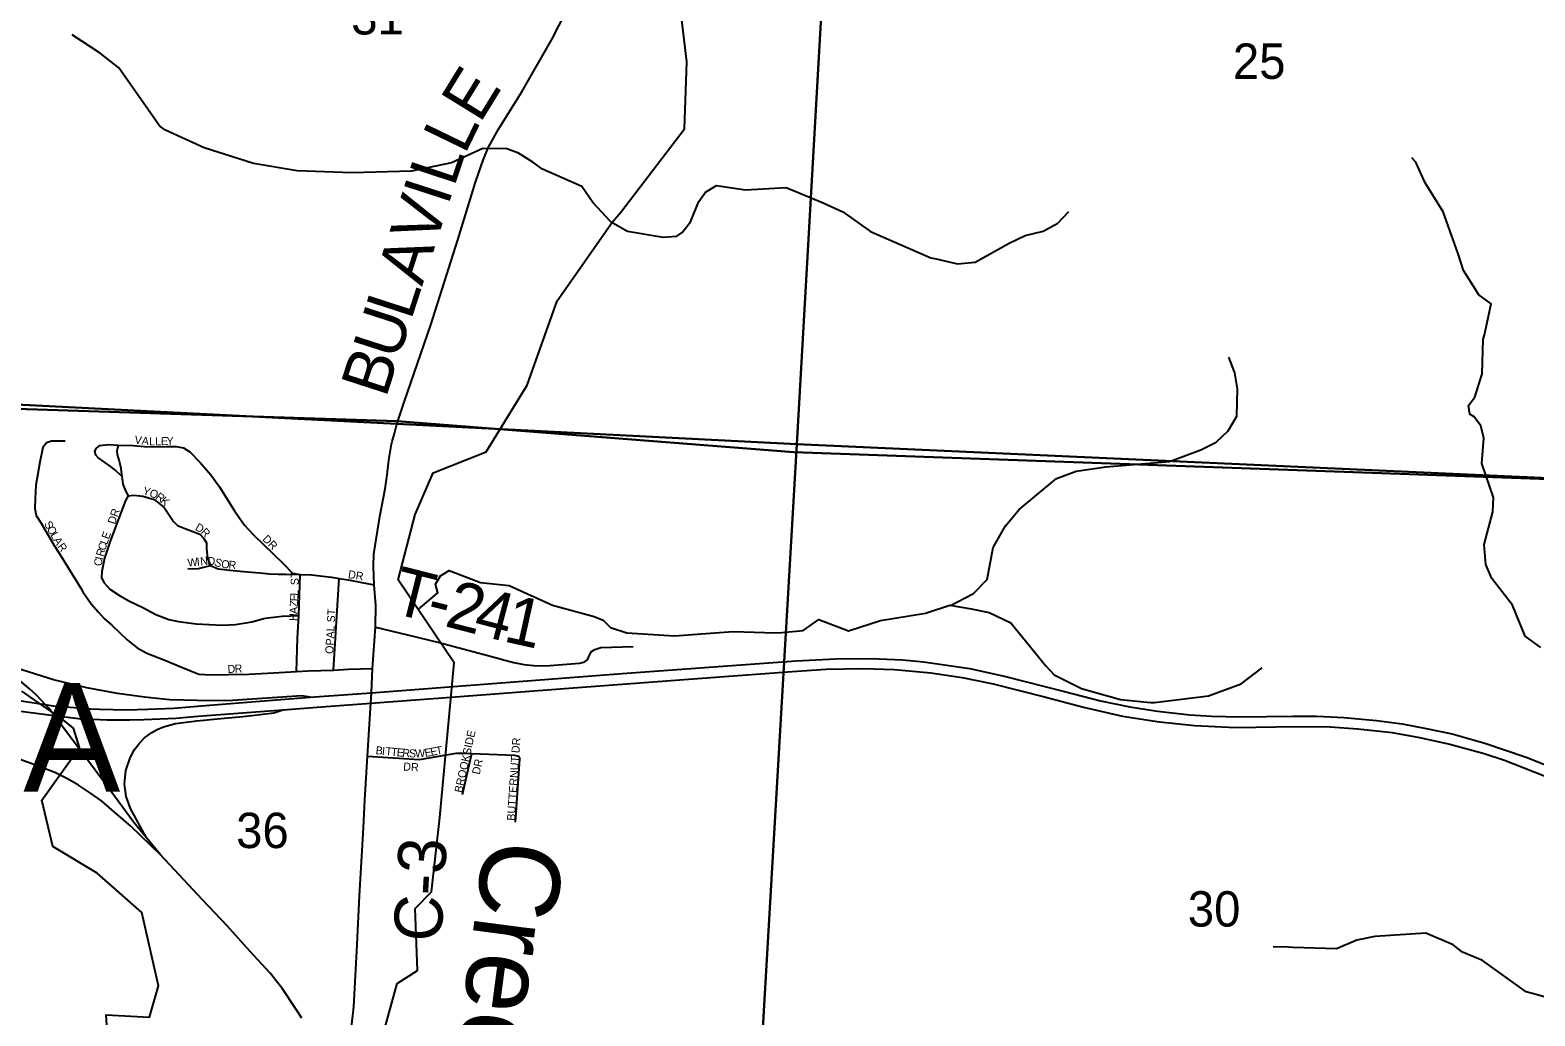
# Model space of a CAD drawing. Extents: x 1878108 to 2183446, y 146837 to 508383.
# Drawn here: x 2047624 to 2057027, y 304899 to 311060 of the extents above; entities that cross this region are included whole.
import ezdxf

# ---------------------------------------------------------------- set-up
doc = ezdxf.new("R2010")
doc.units = 0
for name, color, linetype in [('GM_X_County_Road', 7, 'Continuous'), ('GM_X_County_Road_Text', 7, 'Continuous'), ('GM_X_Interchange_Ramps', 7, 'Continuous'), ('GM_X_Minor_River', 7, 'Continuous'), ('GM_X_Minor_River_Text', 7, 'Continuous'), ('GM_X_Section', 7, 'Continuous'), ('GM_X_Section_Text', 7, 'Continuous'), ('GM_X_State_Route', 7, 'Continuous'), ('GM_X_State_Shield', 7, 'Continuous'), ('GM_X_Township', 7, 'Continuous'), ('GM_X_Township_Road', 7, 'Continuous'), ('GM_X_Township_Road_Text', 7, 'Continuous'), ('GM_X_Township_ROW', 7, 'Continuous'), ('GM_X_Township_Subdivision', 7, 'Continuous'), ('GM_X_Township_Subdivision_Text', 7, 'Continuous'), ('GM_X_US_Route', 7, 'Continuous')]:
    doc.layers.add(name, color=color, linetype=linetype)

msp = doc.modelspace()

# ---------------------------------------------------------------- linework, layer by layer
at = {"layer": 'GM_X_County_Road'}
for points in [[(2049900.5, 308539.7), (2049914, 308588.3), (2049923, 308616.3), (2049961.5, 308735.4), (2050066.6, 309037.3), (2050127.4, 309218.6), (2050297.7, 309749.4), (2050407.2, 310109.9), (2050456.9, 310252.5), (2050489, 310327.7), (2050550.9, 310440.5), (2050695.8, 310674.9), (2050887.1, 311005.6), (2051090.5, 311404.8)], [(2049886.4, 308488.4), (2049900.5, 308539.7)], [(2049772.1, 307646.4), (2049770.2, 307710.4), (2049772.5, 307785.6), (2049808.9, 308020), (2049843.2, 308193.6), (2049855.4, 308279.8), (2049865.3, 308371.6), (2049881.9, 308472.2), (2049886.4, 308488.4)], [(2049520.9, 304582.1), (2049576.5, 304628.2), (2049602.6, 304667.2), (2049614.4, 304708.6), (2049626.2, 304773.7), (2049646.3, 304955.9), (2049667.6, 305345.1), (2049683, 305649.1), (2049706.7, 306075), (2049716.1, 306250.1), (2049732.7, 306522.2), (2049753.9, 306853.8), (2049757.2, 306919.2), (2049764.7, 307070.1), (2049782.4, 307328.9), (2049784.6, 307463.8), (2049773.6, 307593.1), (2049772.1, 307646.4)]]:
    msp.add_lwpolyline(points, dxfattribs=at)
at = {"layer": 'GM_X_Interchange_Ramps'}
for points in [[(2049373.5, 306891.7), (2049322.2, 306899.8), (2048857.3, 306867.2), (2048669, 306869.5), (2048496.5, 306874.9), (2048339, 306891), (2048170.4, 306914.6), (2047978.2, 306949.3), (2047769.9, 307000.1), (2047572.7, 307062.1), (2047428.9, 307110.4), (2047110.9, 307230.7), (2046902.7, 307301.3)], [(2048351.8, 306011.7), (2048251, 306195.3), (2048223.7, 306269.7), (2048215, 306347.9), (2048222.5, 306432.2), (2048248.5, 306511.6), (2048277, 306564.9), (2048306.8, 306604.6), (2048339, 306636.8), (2048384.9, 306670.3), (2048417.2, 306690.1), (2048456.8, 306705), (2048532.5, 306726.1), (2048667, 306743.4), (2048815.5, 306756.8), (2048952.9, 306771.1), (2049008.9, 306776.9), (2049147.3, 306792.4), (2049204, 306812.4)]]:
    msp.add_lwpolyline(points, dxfattribs=at)
at = {"layer": 'GM_X_Minor_River'}
for points in [[(2049624.7, 303298.8), (2049841.3, 304246.1), (2049790, 304642.5), (2049918.2, 305102.6), (2050045.4, 305183.9), (2050030.3, 305570.6), (2050133.2, 305673.7), (2050185.2, 306139.2), (2050274.7, 307106), (2049923.1, 307624), (2050030, 308031.8), (2050142.8, 308293.3), (2050473.9, 308424.6), (2050730.9, 308841.8), (2050918.4, 309368.5), (2051262.7, 309860.7), (2051316.1, 309921.3), (2051714.1, 310442), (2051728.6, 310861), (2051598.1, 311944.1)], [(2051250.9, 309864.2), (2051140.9, 309982.5), (2051070.9, 310082.8), (2050826.8, 310191), (2050764.7, 310235.1), (2050676.7, 310291.2), (2050602.6, 310317.2), (2050452.5, 310319.1), (2050256.3, 310230.5), (2050008.1, 310178), (2049633.9, 310167.6), (2049293.6, 310179.3), (2049019.4, 310225.2), (2048711.2, 310323.2), (2048497.1, 310421.4), (2048465.1, 310437.4), (2048433, 310461.5), (2048179, 310824.6), (2048062.9, 310914.8), (2047886.8, 311029.1)], [(2057064, 307200.5), (2056966, 307272.7), (2056886, 307465.3), (2056758, 307631.8), (2056720, 307720.1), (2056710, 307844.6), (2056764.1, 308049.4), (2056768.2, 308139.8), (2056696.2, 308350.5), (2056708.3, 308509.1), (2056688.3, 308587.4), (2056646.3, 308643.6), (2056620.2, 308659.6), (2056612.3, 308713.8), (2056652.3, 308766), (2056696.4, 308912.6), (2056702.5, 309127.5), (2056712.5, 309155.6), (2056752.6, 309348.4), (2056676.5, 309404.5), (2056580.5, 309557), (2056546.6, 309661.3), (2056454.6, 309924.2), (2056340.6, 310104.8), (2056282.6, 310235.2), (2056258.6, 310261.3)], [(2051250.9, 309864.2), (2051357, 309804.1), (2051579.2, 309766.1), (2051665.2, 309772.3), (2051699.2, 309794.4), (2051751.3, 309860.7), (2051803.4, 309989.2), (2051843.4, 310047.5), (2051913.5, 310087.7), (2052093.6, 310061.8), (2052347.8, 310076.2), (2052580, 309980), (2052702, 309924), (2052876.1, 309801.7), (2053252.3, 309637.5), (2053286.3, 309629.5), (2053418.4, 309599.5), (2053528.5, 309609.7), (2053742.7, 309728.4), (2053842.8, 309776.7), (2053954.9, 309802.9), (2054045, 309853.2), (2054115, 309925.5)], [(2053374.2, 307464.9), (2053519.7, 307539.8), (2053603.8, 307626.2), (2053641.9, 307827), (2053718, 307961.6), (2053804.1, 308064.1), (2054038.4, 308257.1), (2054160.5, 308303.4), (2054346.6, 308329.7), (2054742.9, 308364.3), (2054939, 308436.8), (2055035.1, 308485.1), (2055111.2, 308555.5), (2055165.3, 308647.9), (2055169.3, 308818.5), (2055151.4, 308918.9), (2055113.4, 309015.2)], [(2050048, 307440), (2050171.3, 307542.1), (2050157.3, 307598.3), (2050189.4, 307648.6), (2050243.4, 307682.8), (2050439.5, 307606.7), (2050617.7, 307588.8), (2050887.8, 307466.6), (2051148, 307394.6), (2051206, 307372.6), (2051250, 307326.5), (2051352.1, 307292.5), (2051650.3, 307274.7), (2052016.6, 307301.2), (2052278.8, 307293.5), (2052320.8, 307295.5), (2052454.9, 307307.7), (2052553, 307376.1), (2052737.1, 307306), (2052937.3, 307370.5), (2053219.5, 307417), (2053371.6, 307465.3), (2053503.7, 307443.4), (2053615.8, 307419.4), (2053751.8, 307355.3), (2053969.9, 307086.6), (2054023.9, 307030.4), (2054194, 306946.3), (2054438.1, 306876.3), (2054624.3, 306858.4), (2054650.3, 306858.5), (2054986.5, 306899), (2055190.7, 306973.5), (2055322.8, 307074)], [(2049625.1, 303304.3), (2049060.4, 303573.8), (2049194, 303925.7), (2048546.4, 304250.6), (2048461.8, 304434.2), (2048322.1, 304386.8), (2048133.6, 304391.2), (2048098.8, 304905.9), (2048369.6, 304892.3), (2048427.1, 305087.2), (2048322.9, 305545.3), (2048043, 305791.3), (2047766.3, 305957.2), (2047698.3, 306247.2), (2047932.5, 306575.9), (2047894.8, 306697.9), (2047830, 306749.4), (2047573.1, 306929.5)], [(2058178.1, 305238.4), (2058152.1, 305230.3), (2058078, 305055.5), (2058003.9, 304985.2), (2057873.8, 304995.1), (2057615.6, 304912.5), (2057417.5, 304960.4), (2057175.3, 304994.3), (2056971.2, 305050.3), (2056699.1, 305244.7), (2056575, 305296.7), (2056517, 305342.8), (2056344.9, 305416.9), (2056026.7, 305394.5), (2055914.6, 305372.3), (2055786.5, 305317.9), (2055514.3, 305327.6), (2055484.3, 305329.6), (2055392.2, 305331.5)]]:
    msp.add_lwpolyline(points, dxfattribs=at)
at = {"layer": 'GM_X_Section'}
for points in [[(2047167.4, 313959), (2052709.8, 313676.3), (2052415.9, 308472), (2046921.6, 308750.8)], [(2052709.8, 313676.3), (2058190.2, 313401.4), (2058189.6, 313387.2), (2057942.3, 308221.2), (2052415.9, 308472)], [(2052415.9, 308472), (2052098.8, 303033.5), (2046608.5, 303278.4), (2046921.6, 308750.8)], [(2057942.3, 308221.2), (2057916.7, 307664.9), (2057890.5, 307119.5), (2057859.5, 306520.8), (2057833, 305974.8), (2057806.5, 305428.7), (2057761.9, 304523.6), (2057716.2, 303631), (2057671.2, 302762.9), (2052098.8, 303033.5), (2052415.9, 308472)]]:
    msp.add_lwpolyline(points, close=True, dxfattribs=at)
at = {"layer": 'GM_X_State_Route'}
for points in [[(2047774.9, 306775.7), (2047742.6, 306820.3), (2047719.4, 306845), (2047663.2, 306904.6), (2047618.6, 306945.6), (2047564.4, 306990.5), (2047476, 307049.7), (2047391.7, 307093.1), (2047262.7, 307147.7), (2047085.4, 307222.1), (2046902.7, 307301.3), (2046850.6, 307315.4), (2046713.4, 307351), (2046643.9, 307368.4), (2046597.9, 307375.6)], [(2048109.5, 306327.9), (2047958.9, 306532.7), (2047774.9, 306775.7)], [(2048439.5, 305905.2), (2048253.8, 306084.3), (2048135.9, 306187.2), (2048071.2, 306242.5), (2048001.8, 306292.1), (2047926.1, 306340.4), (2047857.9, 306380.1), (2047778.6, 306419.8), (2047680.6, 306457), (2047539.2, 306510.3)], [(2048439.5, 305905.2), (2048351.8, 306011.7), (2048272.1, 306108.5), (2048156.8, 306263.5), (2048109.5, 306327.9)], [(2049321.7, 304886.1), (2049283.2, 304946.4), (2049201.5, 305068.3), (2049124.6, 305166.5), (2048998.1, 305304.9), (2048854.9, 305461.3), (2048701.1, 305623.7), (2048439.5, 305905.2)]]:
    msp.add_lwpolyline(points, dxfattribs=at)
at = {"layer": 'GM_X_Township'}
for points in [[(2070739.3, 311674.7), (2070547.7, 310380), (2070070.7, 307971.1), (2070016.1, 307669.7), (2069797.4, 307674.9), (2069609.3, 307677.1), (2069237, 307696.5), (2068944.1, 307708.5), (2068514.1, 307728.6), (2068064, 307746.5), (2067786.4, 307749.4), (2067054.1, 307786.6), (2067015.8, 307794.3), (2066035.3, 307838.7), (2065951.8, 307842.4), (2059931.7, 308140), (2058453.5, 308204.9), (2052395.6, 308421.9), (2049918.6, 308616.7), (2046896.4, 308713), (2047299.6, 315671.9)], [(2045292.2, 281208.8), (2045645.1, 286985.8), (2045909.9, 291035.1), (2045984.8, 292287.1), (2046004.2, 292592), (2046274.1, 297148.3), (2046818.9, 306761.3), (2046837.6, 306990.7), (2046850.7, 307315.9), (2046896.4, 308713), (2049918.6, 308616.7), (2052395.6, 308421.9), (2058453.5, 308204.9)]]:
    msp.add_lwpolyline(points, dxfattribs=at)
at = {"layer": 'GM_X_Township_Road'}
for points in [[(2049782.4, 307328.9), (2049982.1, 307280.8), (2050179.2, 307232), (2050328, 307192.3), (2050462, 307157.6), (2050469.9, 307155.4)], [(2050469.9, 307155.4), (2050538.8, 307136.5), (2050590.9, 307121.6), (2050646.7, 307108), (2050710, 307094.4), (2050770.7, 307088.2), (2050803, 307086.9), (2050871.1, 307088.4), (2051057.2, 307103), (2051085.7, 307109.2), (2051106.8, 307125.4), (2051119.2, 307152.6), (2051131.6, 307177.4), (2051152.6, 307189.8), (2051189.8, 307201), (2051392, 307208.4)]]:
    msp.add_lwpolyline(points, dxfattribs=at)
at = {"layer": 'GM_X_Township_ROW'}
for points in [[(2047844, 308491), (2047807.5, 308491), (2047757.7, 308491), (2047725.7, 308480), (2047704.6, 308451.2), (2047684.7, 308360.6), (2047660.4, 308216.8), (2047656.6, 308131.8)], [(2048173.5, 308464.5), (2048119.3, 308468.9), (2048055.2, 308462.3), (2048037.5, 308447.9), (2048027.5, 308428), (2048032, 308404.8), (2048050.8, 308383.8), (2048122.6, 308335.1), (2048159.2, 308305)]]:
    msp.add_lwpolyline(points, dxfattribs=at)
at = {"layer": 'GM_X_Township_Subdivision'}
for points in [[(2048173.5, 308464.5), (2048166.9, 308431.3), (2048168, 308408.1), (2048181.2, 308365), (2048190.1, 308332.9), (2048197.8, 308273.2), (2048204.5, 308222.3), (2048221, 308180.3), (2048237.9, 308150.1)], [(2048173.5, 308464.5), (2048243.2, 308465.6), (2048339.4, 308457.9), (2048398, 308454.5), (2048478.7, 308457.9), (2048537.3, 308456.8), (2048583.7, 308449), (2048621.3, 308424.7), (2048687.7, 308357.2), (2048754, 308279.8), (2048807.1, 308204.6), (2048855.8, 308128.3), (2048902.2, 308055.4), (2048963, 307966.9), (2049017.2, 307908.3), (2049083.6, 307844.2), (2049142.2, 307787.8), (2049205.2, 307726.9), (2049263.8, 307666.1), (2049312.4, 307657.3)], [(2048159.2, 308305), (2048197.8, 308273.2)], [(2047656.6, 308131.8), (2047653.8, 308070.8), (2047662.6, 308026.6), (2047692.5, 307978), (2047775.4, 307838.6), (2047806.4, 307790), (2047940.6, 307571.6)], [(2048237.9, 308150.1), (2048221, 308119.5), (2048191.2, 308043.2), (2048124.8, 307866.3), (2048088.4, 307760.1), (2048071.8, 307676.1), (2048070.7, 307639.6), (2048083.9, 307607.5), (2048121.5, 307565.5), (2048183.5, 307525.7), (2048245.4, 307490.3), (2048328.3, 307450.5), (2048409, 307408.5), (2048492, 307377.5), (2048551.7, 307363.1), (2048661.1, 307349.9), (2048823.7, 307341), (2048906.6, 307344.3), (2049009.5, 307362), (2049092.4, 307384.2), (2049198.6, 307396.3), (2049303.6, 307400.7)], [(2048237.9, 308150.1), (2048271.9, 308152.7), (2048329.4, 308147.1), (2048400.2, 308127.2), (2048462.1, 308076.4), (2048519.6, 307987.9), (2048546.1, 307963.6), (2048597, 307943.7), (2048684.4, 307910.5), (2048709.8, 307882.9), (2048726.4, 307856.3), (2048726.4, 307820.9), (2048733, 307756.8), (2048751.8, 307713.7)], [(2048609.2, 307693.8), (2048676.6, 307696), (2048751.8, 307713.7)], [(2048751.8, 307713.7), (2048799.4, 307693.8), (2048872.4, 307683.8), (2048979.6, 307675), (2049060.3, 307668.3), (2049120, 307662.8), (2049174.2, 307659.5), (2049222.9, 307659.5), (2049312.4, 307657.3), (2049382.1, 307656.2), (2049506.7, 307641.8)], [(2049288.1, 307051.3), (2049294.8, 307259.2), (2049303.6, 307400.7), (2049312.4, 307657.3)], [(2047940.6, 307571.6), (2047954.6, 307548.9), (2048005.4, 307474.8), (2048050.8, 307421.8), (2048087.4, 307383.7), (2048134.8, 307341), (2048231, 307250.4), (2048294, 307198.4), (2048353.7, 307166.3), (2048465.4, 307122.1), (2048566.1, 307081.2), (2048678.8, 307034.7), (2048754, 307031.4), (2048862.3, 307033.4)], [(2049506.7, 307641.8), (2049507.1, 307641.8), (2049554.6, 307633), (2049612.1, 307624.1), (2049697.3, 307607.5), (2049773.6, 307593.1)], [(2049520.3, 307060.2), (2049554.6, 307633)], [(2048862.3, 307033.4), (2048990.7, 307035.8), (2049145.5, 307043.6), (2049288.1, 307051.3), (2049362.2, 307055.7), (2049520.3, 307060.2), (2049613.2, 307066.8), (2049764.7, 307070.1)], [(2049732.7, 306522.2), (2050058, 306502.1), (2050285.7, 306541.4), (2050328.8, 306540.2)], [(2050325.4, 306283.2), (2050383.3, 306538.7)], [(2050328.8, 306540.2), (2050383.3, 306538.7)], [(2050383.3, 306538.7), (2050650.7, 306528.1), (2050676.7, 306523.4), (2050683.8, 306505.6)], [(2050657.8, 306110.5), (2050683.8, 306505.6)]]:
    msp.add_lwpolyline(points, dxfattribs=at)
at = {"layer": 'GM_X_US_Route'}
for points in [[(2047567.8, 306867.4), (2047719.4, 306845), (2047768.6, 306837.7), (2048004.2, 306819.1), (2048058.8, 306815.4), (2048227.4, 306812.9), (2048358.9, 306816.6), (2048522.6, 306822.8), (2048746, 306841.6), (2049373.5, 306891.7), (2049667.3, 306912.3), (2049757.2, 306919.2), (2051323.4, 307039.1), (2052410.2, 307118.2), (2052697.7, 307132.8), (2052928.3, 307131.6), (2053078.4, 307124.1), (2053206.1, 307111.7), (2053495, 307070.8), (2053710.8, 307022.4), (2054087.8, 306925.7), (2054312.2, 306868.7), (2054495.7, 306830.2), (2054668.1, 306803), (2054871.4, 306780.6), (2055005.4, 306772), (2055182.7, 306768.2), (2055513.8, 306772), (2055663.8, 306772.2), (2055832.5, 306764.5), (2056037.1, 306745.9), (2056198.3, 306723.6), (2056348.3, 306696.3), (2056509.5, 306661.6), (2056714.1, 306604.6), (2056972, 306515.3), (2057103.5, 306464.4)], [(2046749.6, 307038.7), (2046810.1, 307013.8), (2046837.7, 307003.9), (2046994.9, 306948), (2047094.1, 306914.6), (2047220.4, 306878.8), (2047287.7, 306859.8), (2047564.4, 306804.2), (2047774.9, 306775.7), (2047926.1, 306758.3), (2048105.9, 306749.6), (2048246, 306749.6), (2048334.1, 306752.1), (2048535, 306760.8), (2048671.5, 306771.9)], [(2050283.2, 306893.9), (2050991.4, 306948), (2051876.8, 307015), (2052385.2, 307052.2), (2052598.5, 307067.1), (2052826.7, 307070.8), (2053025.1, 307064.6), (2053253.2, 307042.3), (2053449.1, 307014.6), (2053641.3, 306975.3), (2053962.5, 306893.5), (2054206.8, 306829), (2054449.8, 306773.2), (2054680.5, 306737.2), (2054902.4, 306714.9), (2055155.4, 306702.5), (2055534.8, 306708.7), (2055747.2, 306705.8), (2055920.5, 306693.8), (2056134.8, 306669.6), (2056304.9, 306639.3), (2056495.9, 306597.1), (2056709.1, 306538.8), (2056837.3, 306498), (2057139.4, 306378.9)], [(2048671.5, 306771.9), (2048840, 306785.6), (2049034.7, 306799.2), (2049204, 306812.4), (2049257.9, 306816.6), (2049445.1, 306831.5), (2049753.9, 306853.8), (2050116, 306881.1), (2050283.2, 306893.9)]]:
    msp.add_lwpolyline(points, dxfattribs=at)

# ---------------------------------------------------------------- texts
at = {"layer": 'GM_X_County_Road_Text'}
for s, rotation, p in [('E', 58.32623, (2050434.6, 310471.8)), ('L', 64.14603, (2050340.6, 310276.9)), ('L', 71.60976, (2050273.7, 310073.5)), ('I', 72.05627, (2050235.9, 309956.9)), ('V', 72.05444, (2050154.6, 309705.8)), ('A', 72.05444, (2050073.2, 309454.6)), ('L', 72.05586, (2050004.1, 309241.1)), ('U', 72.05444, (2049922.8, 308990)), ('B', 72.05504, (2049846.8, 308755.6)), ('C-3', 86.79479, (2050193.2, 305357.6))]:
    msp.add_text(s, height=300, rotation=rotation, dxfattribs=at).set_placement(p)
at = {"layer": 'GM_X_Minor_River_Text'}
msp.add_text('Creek', height=500.03, rotation=262.51455, dxfattribs=at).set_placement((2050468.8, 306017.3))
at = {"layer": 'GM_X_Section_Text'}
for s, p in [('31', (2049630.9, 311032.3)), ('25', (2055139.7, 310755.1)), ('36', (2048911.5, 305948.1)), ('30', (2054858.1, 305457.5))]:
    msp.add_text(s, height=221, rotation=0.00001, dxfattribs=at).set_placement(p)
at = {"layer": 'GM_X_State_Shield'}
msp.add_text('160A', height=680, dxfattribs=at).set_placement((2046064.4, 306300.6))
at = {"layer": 'GM_X_Township_Road_Text'}
for s, rotation, p in [('T', 345.94722, (2049871.4, 307420.5)), ('2', 345.60081, (2050206.7, 307336.5)), ('-', 345.92109, (2050088.7, 307366.1)), ('4', 345.24485, (2050383.8, 307291)), ('1', 347.54773, (2050573.8, 307241.3))]:
    msp.add_text(s, height=300, rotation=rotation, dxfattribs=at).set_placement(p)
at = {"layer": 'GM_X_Township_Subdivision_Text'}
for s, rotation, p in [('V', 352.61476, (2048274.8, 308476.1)), ('A', 353.93178, (2048319.7, 308470.3)), ('L', 357.52964, (2048366.9, 308465.3)), ('L', 2.40337, (2048406.7, 308463.8)), ('E', 2.4784, (2048442, 308465.3)), ('Y', 0.67764, (2048476.7, 308466.8)), ('Y', 344.06061, (2048324.4, 308159)), ('O', 340.03744, (2048365.8, 308147.2)), ('R', 323.66915, (2048403.8, 308134)), ('K', 319.13077, (2048434.9, 308111.2)), ('DR', 71.56504, (2048154.6, 307968.1)), ('S', 299.60932, (2047709.7, 307974.2)), ('O', 299.60662, (2047727.1, 307943.6)), ('D', 330.08973, (2048651, 307938.7)), ('R', 314.43342, (2048686.3, 307919)), ('L', 299.59582, (2047748.9, 307905.3)), ('A', 301.33189, (2047767.1, 307873.3)), ('R', 305.54063, (2047792.2, 307832.4)), ('C', 72.20258, (2048093.3, 307803.6)), ('L', 71.686, (2048105.4, 307841.2)), ('E', 70.416, (2048116.4, 307874.3)), ('DR', 315, (2049072.2, 307875)), ('C', 80.13834, (2048070.6, 307707)), ('I', 76.85461, (2048077.3, 307745.3)), ('R', 73.34727, (2048082.1, 307765.9)), ('W', 6.16566, (2048611, 307706.1)), ('I', 6.13258, (2048667.8, 307712.2)), ('N', 6.16436, (2048689.7, 307714.6)), ('D', 354.13284, (2048730.7, 307719.3)), ('S', 339.66453, (2048771.2, 307715.5)), ('O', 352.8126, (2048816.4, 307700.3)), ('R', 355.34121, (2048862.4, 307694.6)), ('ST', 90, (2049302.5, 307591.2)), ('DR', 351.03092, (2049608.2, 307635.6)), ('L', 87.04752, (2049300, 307524.3)), ('Z', 87.07481, (2049296.4, 307454)), ('E', 87.07481, (2049298.2, 307489.2)), ('H', 89.10379, (2049293.7, 307366.6)), ('A', 87.39842, (2049294.4, 307410.2)), ('OPAL ST', 86.93128, (2049518.1, 307160.5)), ('D', 2.6234, (2048859.3, 307041.8)), ('R', 2.86371, (2048903.5, 307043.8)), ('BROOKSIDE', 77.7037, (2050323.5, 306290.8)), ('BUTTERNUT DR', 86.18591, (2050653.3, 306117.8)), ('B', 354.72585, (2049781.8, 306535.1)), ('I', 354.72585, (2049821.2, 306531.4)), ('T', 354.72585, (2049843.1, 306529.4)), ('T', 354.72585, (2049878.1, 306526.2)), ('E', 354.72585, (2049913.2, 306522.9)), ('R', 354.72585, (2049948.2, 306519.7)), ('S', 357.43882, (2049990.3, 306515.9)), ('W', 2.86478, (2050030.6, 306514.3)), ('E', 8.29073, (2050092.9, 306517.7)), ('E', 11.0037, (2050130.3, 306523.2)), ('T', 11.0037, (2050164.8, 306529.9)), ('DR', 356.97755, (2049954.7, 306433.2)), ('DR', 77.46475, (2050433, 306404.3))]:
    msp.add_text(s, height=50, rotation=rotation, dxfattribs=at).set_placement(p)

doc.saveas('drawing.dxf')
